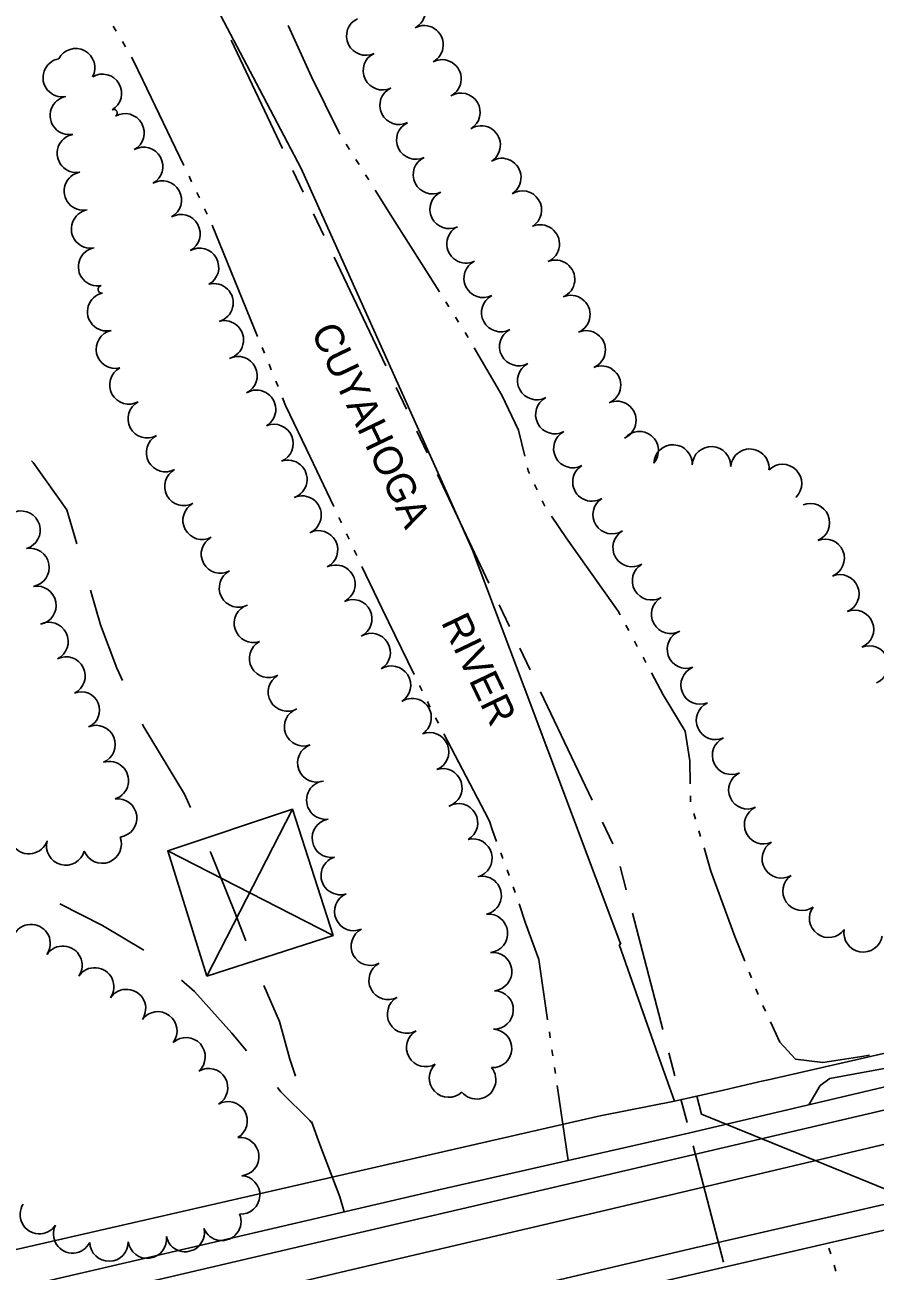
# Model space of a CAD drawing. Extents: x -25029 to 2274964, y -81170 to 687028.
# Drawn here: x -2473 to -2031, y -68386 to -67738 of the extents above; entities that cross this region are included whole.
import ezdxf

# ---------------------------------------------------------------- set-up
doc = ezdxf.new("R2010")
doc.units = 0
for name, color, linetype in [('81911BEA - RW_X_Fee_RW', 7, 'Continuous'), ('BRIDGE', 7, 'Continuous'), ('DIVISIONS', 7, 'Continuous'), ('DRIVWY', 7, 'Continuous'), ('DV_X_Corp_Line', 7, 'Continuous'), ('GE_X_CL_2000', 7, 'Continuous'), ('INTERSTATE', 7, 'Continuous'), ('ROAD-NAME', 7, 'Continuous'), ('TRANSPWRLN', 7, 'Continuous'), ('TREES', 7, 'Continuous'), ('WATER', 7, 'Continuous')]:
    doc.layers.add(name, color=color, linetype=linetype)

msp = doc.modelspace()

# ---------------------------------------------------------------- linework, layer by layer
at = {"layer": '81911BEA - RW_X_Fee_RW'}
for points in [[(-2135.26, -68297.43), (-2109.72, -68291.6), (-2089.08, -68286.89), (-2087.22, -68286.46), (-1516.73, -68156.13)], [(-2135.26, -68297.43), (-2173.87, -68305.04), (-2175.39, -68305.38), (-2479.85, -68374.94)]]:
    msp.add_lwpolyline(points, dxfattribs=at)
at = {"layer": 'BRIDGE'}
for points in [[(-3072.93, -68532.18), (-2986.08, -68512.39), (-2887.63, -68489.44), (-2737.89, -68454.59), (-2575.28, -68417.21), (-2419.92, -68381.2), (-2257.8, -68343.47), (-2127.95, -68314), (-1959.59, -68274.3), (-1799.51, -68236.35), (-1543.09, -68178.2), (-1365.38, -68136.26), (-1153.86, -68086.44), (-897.08, -68026.56), (-730.24, -67988.23), (-623.47, -67963.21), (-490.22, -67932.55), (-343.74, -67898.85), (-190.99, -67863.34), (-183.59, -67861.62), (251.64, -67759.9)], [(251.64, -67834.66), (-182.74, -67935.72), (-257.97, -67953.08), (-436.39, -67994.66), (-623.1, -68037.62), (-805.84, -68079.78), (-1089.02, -68146.09), (-1276.8, -68189.34), (-1445.59, -68229.61), (-1643.44, -68275.61), (-1832.44, -68320.22), (-1941.48, -68344.79), (-2128.81, -68388.19), (-2345.02, -68437.86), (-2439.82, -68460.28), (-2586.12, -68493.59), (-2734.18, -68527.96), (-2887.79, -68563.41), (-3056.3, -68603.08)]]:
    msp.add_lwpolyline(points, dxfattribs=at)
at = {"layer": 'DIVISIONS'}
for p, q in [((-2365.81, -67745.86), (-2338.99, -67802.31)), ((-2333.63, -67813.6), (-2328.26, -67824.89)), ((-2322.9, -67836.18), (-2317.53, -67847.47)), ((-2312.17, -67858.76), (-2285.35, -67915.22)), ((-2279.99, -67926.51), (-2274.62, -67937.8)), ((-2269.26, -67949.09), (-2263.89, -67960.38)), ((-2258.53, -67971.67), (-2231.71, -68028.12)), ((-2226.35, -68039.41), (-2220.98, -68050.7)), ((-2215.62, -68061.99), (-2210.25, -68073.29)), ((-2204.89, -68084.58), (-2178.07, -68141.03)), ((-2172.7, -68152.32), (-2167.34, -68163.61)), ((-2163.44, -68175.43), (-2160.28, -68187.53)), ((-2157.13, -68199.62), (-2141.34, -68260.1)), ((-2138.18, -68272.19), (-2135.02, -68284.28)), ((-2131.86, -68296.38), (-2128.7, -68308.47)), ((-2125.54, -68320.57), (-2109.75, -68381.04))]:
    msp.add_line(p, q, dxfattribs=at)
at = {"layer": 'DRIVWY'}
for points in [[(-2445.94, -68007.77), (-2451.11, -67990.02), (-2468.61, -67965.51), (-2469.59, -67964.51)], [(-2422.2, -68078.81), (-2425.2, -68072.27), (-2433.72, -68049.84), (-2438.96, -68031.77)], [(-2386.82, -68144.8), (-2389.94, -68137.86), (-2411.45, -68102.24), (-2411.78, -68101.53)], [(-2358.17, -68214.09), (-2363.64, -68199.69), (-2376.26, -68168.32), (-2376.58, -68167.61)], [(-2454.9, -68194.89), (-2432.6, -68206.02), (-2411.07, -68218.86)], [(-2391.61, -68234.44), (-2384.83, -68240.43), (-2365.35, -68262.08), (-2357.76, -68271.15)], [(-2332.28, -68284.33), (-2335.31, -68275.56), (-2340.55, -68256.03), (-2348.7, -68237.22)], [(-2341.72, -68290.33), (-2339.88, -68292.53), (-2324.87, -68307.41), (-2323.53, -68309.13)], [(-2306.98, -68354.91), (-2309.2, -68347.15), (-2319.59, -68319.86), (-2323.97, -68307.91)]]:
    msp.add_lwpolyline(points, dxfattribs=at)
at = {"layer": 'DV_X_Corp_Line'}
for p, q in [((-2394.99, -67687.73), (-2350.78, -67771.76)), ((-2394.99, -67687.73), (-2350.78, -67771.76)), ((-2350.78, -67771.76), (-2394.99, -67687.73)), ((-2350.78, -67771.76), (-2394.99, -67687.73)), ((-2350.78, -67771.76), (-2329.31, -67812.58)), ((-2350.78, -67771.76), (-2329.31, -67812.58)), ((-2329.31, -67812.58), (-2350.78, -67771.76)), ((-2329.31, -67812.58), (-2350.78, -67771.76)), ((-2329.31, -67812.58), (-2256.76, -67974.11)), ((-2329.31, -67812.58), (-2256.76, -67974.11)), ((-2256.76, -67974.11), (-2329.31, -67812.58)), ((-2256.76, -67974.11), (-2329.31, -67812.58)), ((-2256.76, -67974.11), (-2240.19, -68011.01)), ((-2256.76, -67974.11), (-2240.19, -68011.01)), ((-2240.19, -68011.01), (-2256.76, -67974.11)), ((-2240.19, -68011.01), (-2256.76, -67974.11)), ((-2240.19, -68011.01), (-2213.38, -68082.25)), ((-2240.19, -68011.01), (-2213.38, -68082.25)), ((-2213.38, -68082.25), (-2240.19, -68011.01)), ((-2213.38, -68082.25), (-2240.19, -68011.01)), ((-2213.38, -68082.25), (-2163.57, -68214.59)), ((-2213.38, -68082.25), (-2163.57, -68214.59)), ((-2163.57, -68214.59), (-2213.38, -68082.25)), ((-2163.57, -68214.59), (-2213.38, -68082.25)), ((-2163.12, -68215.78), (-2163.98, -68215.9)), ((-2163.12, -68215.78), (-2163.98, -68215.9)), ((-2163.98, -68215.9), (-2163.12, -68215.78)), ((-2163.98, -68215.9), (-2163.12, -68215.78)), ((-2163.98, -68215.9), (-2143.84, -68273.09)), ((-2163.98, -68215.9), (-2143.84, -68273.09)), ((-2143.84, -68273.09), (-2163.98, -68215.9)), ((-2143.84, -68273.09), (-2163.98, -68215.9)), ((-2163.57, -68214.59), (-2163.12, -68215.78)), ((-2163.57, -68214.59), (-2163.12, -68215.78)), ((-2163.12, -68215.78), (-2163.57, -68214.59)), ((-2163.12, -68215.78), (-2163.57, -68214.59)), ((-2143.84, -68273.09), (-2135.26, -68297.43)), ((-2143.84, -68273.09), (-2135.26, -68297.43)), ((-2135.26, -68297.43), (-2143.84, -68273.09)), ((-2135.26, -68297.43), (-2143.84, -68273.09)), ((-2135.26, -68297.43), (-2123.59, -68294.77)), ((-2135.26, -68297.43), (-2123.59, -68294.77)), ((-2123.59, -68294.77), (-2135.26, -68297.43)), ((-2123.59, -68294.77), (-2135.26, -68297.43)), ((-2123.59, -68294.77), (-2121.11, -68304.08)), ((-2123.59, -68294.77), (-2121.11, -68304.08)), ((-2121.11, -68304.08), (-2123.59, -68294.77)), ((-2121.11, -68304.08), (-2123.59, -68294.77)), ((-2121.11, -68304.08), (-1975.87, -68363.5)), ((-2121.11, -68304.08), (-1975.87, -68363.5)), ((-1975.87, -68363.5), (-2121.11, -68304.08)), ((-1975.87, -68363.5), (-2121.11, -68304.08))]:
    msp.add_line(p, q, dxfattribs=at)
at = {"layer": 'GE_X_CL_2000'}
for points in [[(439.1, -67744.44), (271.13, -67782.96), (149.58, -67812.48), (17.43, -67842.69), (-122.95, -67875.44), (-216.56, -67897.9), (-360.26, -67931.32), (-544.39, -67974.37), (-602.61, -67987.66), (-642.53, -67996.73), (-748.17, -68020.71), (-874.98, -68051.65), (-895.87, -68056.74), (-988, -68076.91), (-1113.01, -68106.01), (-1212.97, -68129.54), (-1341.37, -68158.49), (-1456.06, -68186.54), (-1603.06, -68219.65), (-1765.82, -68259.95), (-1819.85, -68271.59), (-2027.92, -68320.25), (-2060.09, -68327.84)], [(-2060.09, -68327.84), (-2173.63, -68354.65), (-2305.56, -68385.6), (-2493.26, -68429.96), (-2612.59, -68458.45), (-2760.3, -68494.78), (-2908.55, -68528.64), (-3036.52, -68557.57), (-3096.24, -68570.96), (-3147.76, -68582.62), (-3211.88, -68597.51), (-3246.5, -68602.58), (-3282.35, -68607.83)]]:
    msp.add_lwpolyline(points, dxfattribs=at)
at = {"layer": 'INTERSTATE'}
for points in [[(-1956.62, -68285.84), (-2152.46, -68331.5), (-2240.65, -68352.19), (-2333.76, -68373.84), (-2446.4, -68400.09), (-2598.54, -68435.63), (-2764.02, -68473.48), (-2935.34, -68513.06), (-3037.44, -68537.2), (-3157.03, -68562.5), (-3238.18, -68579.02), (-3326.91, -68596.06), (-3390.63, -68607.74), (-3535.91, -68632.92), (-3629.05, -68647.34), (-3713.06, -68659.63), (-3759.13, -68665.72), (-3809.28, -68672.14), (-3832.45, -68674.34), (-3857.87, -68676.39), (-3875.11, -68677.64)], [(-3731.52, -68748.36), (-3579.19, -68712.66), (-3434.43, -68678), (-3287.56, -68644.19), (-3123.41, -68606.33), (-3032.55, -68584.39), (-2874.59, -68548.32), (-2726.25, -68513.54), (-2630.82, -68491.06), (-2475.52, -68455.47), (-2313.2, -68417.6), (-2195.22, -68390.31), (-2126.84, -68374.09), (-1944.67, -68332.37)]]:
    msp.add_lwpolyline(points, dxfattribs=at)
at = {"layer": 'TRANSPWRLN'}
for p, q in [((-2378.44, -68232.45), (-2333.86, -68145.64)), ((-2312.75, -68211.33), (-2398.69, -68167.2))]:
    msp.add_line(p, q, dxfattribs=at)
msp.add_lwpolyline([(-2378.44, -68232.45), (-2398.69, -68167.2), (-2333.86, -68145.64), (-2312.75, -68211.33), (-2378.44, -68232.45)], dxfattribs=at)
at = {"layer": 'TREES'}
for centre, radius, start, end in [((-2274.77, -67730.66), 10, 297.80012, 117.80012), ((-2295.77, -67743.78), 10, 115.71634, 295.71634), ((-2265.45, -67748.35), 10, 297.80012, 117.80012), ((-2446.59, -67760.27), 10, 332.06005, 152.06005), ((-2287.09, -67761.8), 10, 115.71634, 295.71634), ((-2453.58, -67765.41), 10, 100.60113, 280.60113), ((-2256.12, -67766.04), 10, 297.80012, 117.80012), ((-2432.69, -67773.57), 10, 300.4151, 120.4151), ((-2278.41, -67779.81), 10, 115.71634, 295.71634), ((-2246.28, -67783.45), 10, 301.12651, 121.12651), ((-2449.9, -67785.07), 10, 100.60113, 280.60113), ((-2426.74, -67783.78), 1.81, 299.09966, 119.09966), ((-2421, -67794.1), 10, 299.09966, 119.09966), ((-2269.74, -67797.83), 10, 115.71634, 295.71634), ((-2235.75, -67800.44), 10, 302.46545, 122.46545), ((-2446.22, -67804.73), 10, 100.60113, 280.60113), ((-2411.27, -67811.58), 10, 299.09966, 119.09966), ((-2261.06, -67815.85), 10, 115.71634, 295.71634), ((-2225.01, -67817.32), 10, 302.46545, 122.46545), ((-2442.54, -67824.38), 10, 100.60113, 280.60113), ((-2401.55, -67829.05), 10, 299.09966, 119.09966), ((-2252.38, -67833.87), 10, 115.71634, 295.71634), ((-2214.33, -67834.23), 10, 302.09, 122.09), ((-2438.86, -67844.04), 10, 100.60113, 280.60113), ((-2391.85, -67846.55), 10, 298.88355, 118.88355), ((-2243.59, -67851.83), 10, 116.4214, 296.4214), ((-2205.03, -67851.87), 10, 293.48305, 113.48305), ((-2435.18, -67863.7), 10, 100.60113, 280.60113), ((-2382.19, -67864.06), 10, 298.88336, 118.88336), ((-2234.69, -67869.75), 10, 116.4215, 296.4215), ((-2197.06, -67870.22), 10, 293.48305, 113.48305), ((-2433.04, -67875.44), 1.94, 99.14208, 279.14208), ((-2374.67, -67882.45), 10, 285.60377, 105.60377), ((-2430.47, -67887.1), 10, 103.03867, 283.03867), ((-2225.56, -67887.54), 10, 117.92542, 297.92542), ((-2189.1, -67888.56), 10, 293.48305, 113.48305), ((-2369.29, -67901.71), 10, 285.60377, 105.60377), ((-2216.19, -67905.21), 10, 117.92542, 297.92542), ((-2425.96, -67906.58), 10, 103.05697, 283.05697), ((-2181.13, -67906.9), 10, 293.48305, 113.48305), ((-2362.19, -67920.31), 10, 296.19801, 116.19801), ((-2206.83, -67922.88), 10, 117.92542, 297.92542), ((-2173.16, -67925.25), 10, 293.48305, 113.48305), ((-2418.93, -67925.12), 10, 118.44081, 298.44081), ((-2352.54, -67937.81), 10, 301.54719, 121.54719), ((-2409.41, -67942.7), 10, 118.44081, 298.44081), ((-2197.46, -67940.55), 10, 117.92542, 297.92542), ((-2165.19, -67943.59), 10, 293.48305, 113.48305), ((-2343.46, -67955.56), 10, 292.67177, 112.67177), ((-2399.88, -67960.29), 10, 118.44081, 298.44081), ((-2188.09, -67958.22), 10, 117.92542, 297.92542), ((-2153.58, -67959.24), 10, 319.62041, 139.62041), ((-2135.98, -67966.21), 10, 357.16135, 177.16135), ((-2116, -67967.14), 10, 357.51385, 177.51385), ((-2096.05, -67968.42), 10, 355.16472, 175.16472), ((-2336.26, -67974.21), 10, 289.52446, 109.52446), ((-2178.17, -67975.58), 10, 121.57832, 301.57832), ((-2079.04, -67976.37), 10, 314.73315, 134.73315), ((-2390.36, -67977.88), 10, 118.44081, 298.44081), ((-2380.83, -67995.46), 10, 118.44081, 298.44081), ((-2328.87, -67992.78), 10, 293.86656, 113.86656), ((-2167.61, -67992.56), 10, 122.20268, 302.20268), ((-2072, -67983.47), 0.0000000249, 314.72722, 134.72722), ((-2064.54, -67996.74), 10, 292.46997, 112.46997), ((-2475.03, -68000.6), 10, 286.62943, 106.62943), ((-2371.32, -68013.03), 9.98, 118.44081, 298.44081), ((-2320.29, -68010.84), 10, 296.96708, 116.96708), ((-2157.24, -68009.65), 10, 120.27704, 300.27704), ((-2056.9, -68015.22), 10, 292.46997, 112.46997), ((-2470.36, -68020.01), 10, 280.42008, 100.42008), ((-2311.32, -68028.71), 10, 296.33349, 116.33349), ((-2147.15, -68026.93), 10, 120.27704, 300.27704), ((-2361.93, -68030.67), 10, 117.59856, 297.59856), ((-2049.25, -68033.7), 10, 292.46997, 112.46997), ((-2466.73, -68039.68), 10, 280.51289, 100.51289), ((-2302.51, -68046.67), 10, 295.92478, 115.92478), ((-2137.24, -68044.3), 10, 119.11616, 299.11616), ((-2354.19, -68049.04), 10, 108.11219, 288.11219), ((-2041.61, -68052.18), 10, 292.46997, 112.46997), ((-2460.48, -68058.48), 10, 296.28932, 116.28932), ((-2292.95, -68064.21), 10, 301.27606, 121.27606), ((-2129.03, -68062.46), 10, 109.5677, 289.5677), ((-2346.26, -68067.3), 10, 118.80264, 298.80264), ((-2033.96, -68070.67), 10, 292.46997, 112.46997), ((-2451.64, -68076.42), 10, 296.13571, 116.13571), ((-2282.39, -68081.19), 10, 302.47748, 122.47748), ((-2336.49, -68084.75), 10, 119.68462, 299.68462), ((-2121.88, -68081.13), 10, 112.3506, 292.3506), ((-2443.57, -68094.11), 9.45, 292.81301, 112.81301), ((-2271.65, -68098.06), 10, 302.47272, 122.47272), ((-2113.89, -68099.46), 10, 114.73368, 294.73368), ((-2328.07, -68102.82), 10, 110.28946, 290.28946), ((-2436.03, -68112.04), 10, 292.81301, 112.81301), ((-2262.57, -68115.79), 10, 291.79292, 111.79292), ((-2105.52, -68117.63), 10, 114.73368, 294.73368), ((-2321.19, -68121.6), 10, 109.97226, 289.97226), ((-2429.09, -68130.78), 10, 287.85236, 107.85236), ((-2255.66, -68134.55), 10, 288.61369, 108.61369), ((-2097.21, -68135.68), 9.87, 114.73368, 294.73368), ((-2316.53, -68140.92), 10, 97.18178, 277.18178), ((-2424.76, -68150.22), 10, 277.26758, 97.26758), ((-2247.51, -68152.71), 10, 299.76602, 119.76602), ((-2088.89, -68153.73), 10, 114.73368, 294.73368), ((-2470.85, -68158.83), 10, 160.47304, 340.47304), ((-2313.66, -68160.71), 10, 99.31994, 279.31994), ((-2432.81, -68163.77), 10, 201.3176, 21.3176), ((-2240.02, -68171.06), 10, 284.62337, 104.62337), ((-2451.77, -68164.79), 10, 164.81082, 344.81082), ((-2079.65, -68171.44), 10, 120.39031, 300.39031), ((-2309.03, -68180.11), 10, 107.49846, 287.49846), ((-2235.24, -68190.48), 10, 283.00994, 103.00994), ((-2068.87, -68188.27), 10, 124.86991, 304.86991), ((-2302.01, -68198.81), 10, 113.66639, 293.66639), ((-2231.93, -68210.16), 10, 276.09543, 96.09543), ((-2055.06, -68202.35), 10, 144.0123, 324.0123), ((-2469.77, -68215.49), 10, 325.75931, 145.75931), ((-2293.37, -68216.84), 10, 117.51385, 297.51385), ((-2037.12, -68209.93), 10, 170.1861, 350.1861), ((-2453.23, -68226.75), 10, 325.75931, 145.75931), ((-2229.8, -68230.05), 10, 276.09543, 96.09543), ((-2284.13, -68234.58), 10, 117.5206, 297.5206), ((-2436.7, -68238), 10, 325.75931, 145.75931), ((-2420.17, -68249.25), 10, 325.75931, 145.75931), ((-2274.53, -68252.12), 10, 119.87014, 299.87014), ((-2229.02, -68249.99), 10, 268.4258, 88.4258), ((-2403.89, -68260.86), 10, 323.26109, 143.26109), ((-2389.22, -68274.31), 10, 311.68914, 131.68914), ((-2264.57, -68269.46), 10, 119.87426, 299.87426), ((-2229.83, -68269.97), 10, 266.93005, 86.93005), ((-2252.71, -68285.38), 10, 133.4957, 313.4957), ((-2377.49, -68290.39), 10, 300.52516, 120.52516), ((-2238.09, -68286.3), 10, 219.36702, 39.36702), ((-2367.33, -68307.62), 10, 300.52516, 120.52516), ((-2361.26, -68326.19), 10, 275.71612, 95.71612), ((-2360.79, -68346.12), 10, 266.96074, 86.96074), ((-2465.5, -68356.38), 10, 146.68409, 326.68409), ((-2370.6, -68359.85), 10, 201.96694, 21.96694), ((-2448.19, -68366.34), 10, 153.45019, 333.45019), ((-2409.35, -68369.08), 10, 187.86712, 7.86712), ((-2389.65, -68365.65), 10, 191.88813, 11.88813), ((-2429.25, -68370.63), 10, 181.04223, 1.04223)]:
    msp.add_arc(centre, radius, start, end, dxfattribs=at)
at = {"layer": 'WATER'}
for p, q in [((-2427.09, -67738.65), (-2425.5, -67741.34)), ((-2422.32, -67746.72), (-2420.74, -67749.41)), ((-2304.2, -67802.71), (-2305.87, -67800.07)), ((-2299.21, -67810.64), (-2300.87, -67808)), ((-2387.65, -67816.69), (-2386.3, -67819.51)), ((-2294.22, -67818.58), (-2295.88, -67815.93)), ((-2383.6, -67825.15), (-2382.25, -67827.97)), ((-2379.55, -67833.6), (-2378.2, -67836.42)), ((-2375.6, -67842.1), (-2351.96, -67899.96)), ((-2252.48, -67884.62), (-2254.15, -67881.98)), ((-2247.46, -67892.54), (-2249.13, -67889.9)), ((-2242.56, -67900.53), (-2244.15, -67897.84)), ((-2349.6, -67905.75), (-2348.42, -67908.64)), ((-2346.05, -67914.42), (-2344.87, -67917.32)), ((-2342.51, -67923.1), (-2341.33, -67926)), ((-2206.64, -67979.66), (-2207.96, -67976.83)), ((-2202.7, -67988.17), (-2204.01, -67985.33)), ((-2309.74, -67993.99), (-2308.41, -67996.82)), ((-2305.73, -68002.47), (-2304.4, -68005.29)), ((-2301.72, -68010.94), (-2300.39, -68013.77)), ((-2158.98, -68052.83), (-2160.46, -68050.07)), ((-2154.55, -68061.08), (-2156.03, -68058.33)), ((-2150.11, -68069.34), (-2151.59, -68066.59)), ((-2267.82, -68081.33), (-2266.45, -68084.13)), ((-2259.44, -68098.1), (-2258, -68100.87)), ((-2126.85, -68141.8), (-2126.91, -68138.67)), ((-2124.28, -68150.8), (-2125.16, -68147.81)), ((-2121.63, -68159.8), (-2122.51, -68156.8)), ((-2225.52, -68168.32), (-2224.44, -68171.25)), ((-2222.27, -68177.12), (-2221.19, -68180.05)), ((-2219.03, -68185.91), (-2218.03, -68188.87)), ((-2095.2, -68233.26), (-2096.38, -68230.37)), ((-2091.68, -68241.95), (-2092.85, -68239.05)), ((-2087.94, -68250.55), (-2089.24, -68247.7)), ((-2200.29, -68261.38), (-2199.84, -68264.47)), ((-2198.94, -68270.66), (-2198.49, -68273.75)), ((-2197.59, -68279.94), (-2197.14, -68283.03)), ((-2196.24, -68289.21), (-2190.57, -68328.21)), ((-2054, -68376.71), (-2054.97, -68373.74)), ((-2051.31, -68385.69), (-2052.15, -68382.68))]:
    msp.add_line(p, q, dxfattribs=at)
for points in [[(-2309.2, -67794.78), (-2309.81, -67793.8), (-2324.02, -67764.92), (-2336.06, -67738.36)], [(-2417.56, -67754.8), (-2416.62, -67756.39), (-2411.61, -67766.68), (-2390.35, -67811.06)], [(-2257.49, -67876.7), (-2281.83, -67838.26), (-2290.89, -67823.87)], [(-2213.05, -67962.14), (-2216.26, -67948.71), (-2224.97, -67930.38), (-2239.39, -67905.92)], [(-2338.99, -67931.79), (-2337.49, -67935.84), (-2326.51, -67958.56), (-2312.42, -67988.34)], [(-2210.59, -67971.16), (-2211.22, -67969.8), (-2211.6, -67968.22)], [(-2163.42, -68044.57), (-2164.44, -68042.67), (-2191.5, -68004.63), (-2199.23, -67993.36)], [(-2297.71, -68019.42), (-2287.26, -68041.51), (-2270.57, -68075.71)], [(-2127.05, -68132.43), (-2127.3, -68120.59), (-2129.59, -68105.01), (-2141.05, -68086.21), (-2147.15, -68074.85)], [(-2263.71, -68089.75), (-2262.53, -68092.17), (-2262.33, -68092.55)], [(-2255.11, -68106.41), (-2233.81, -68147.27), (-2231.38, -68151.84), (-2229.79, -68156.76), (-2227.69, -68162.46)], [(-2098.73, -68224.57), (-2103.91, -68211.8), (-2116.29, -68177.88), (-2119.86, -68165.79)], [(-2216.02, -68194.79), (-2212.62, -68204.79), (-2205.76, -68223.77), (-2201.19, -68255.2)], [(-2033.8, -68273.55), (-2037.88, -68274.13), (-2058.05, -68277.34), (-2072.27, -68275.51), (-2080.52, -68266.8), (-2085.35, -68256.23)], [(-2065.33, -68299.23), (-2059.43, -68289.26), (-2054.39, -68285.59), (-2019.53, -68279.17), (-2010.67, -68276.55)]]:
    msp.add_lwpolyline(points, dxfattribs=at)

# ---------------------------------------------------------------- texts
at = {"layer": 'ROAD-NAME'}
for s, p in [('CUYAHOGA', (-2324.5, -67897.35)), ('RIVER', (-2256.8, -68048.38))]:
    msp.add_text(s, height=14.99, rotation=295.57563, dxfattribs=at).set_placement(p)

doc.saveas('drawing.dxf')
